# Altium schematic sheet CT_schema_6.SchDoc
size 274 x 160 mm
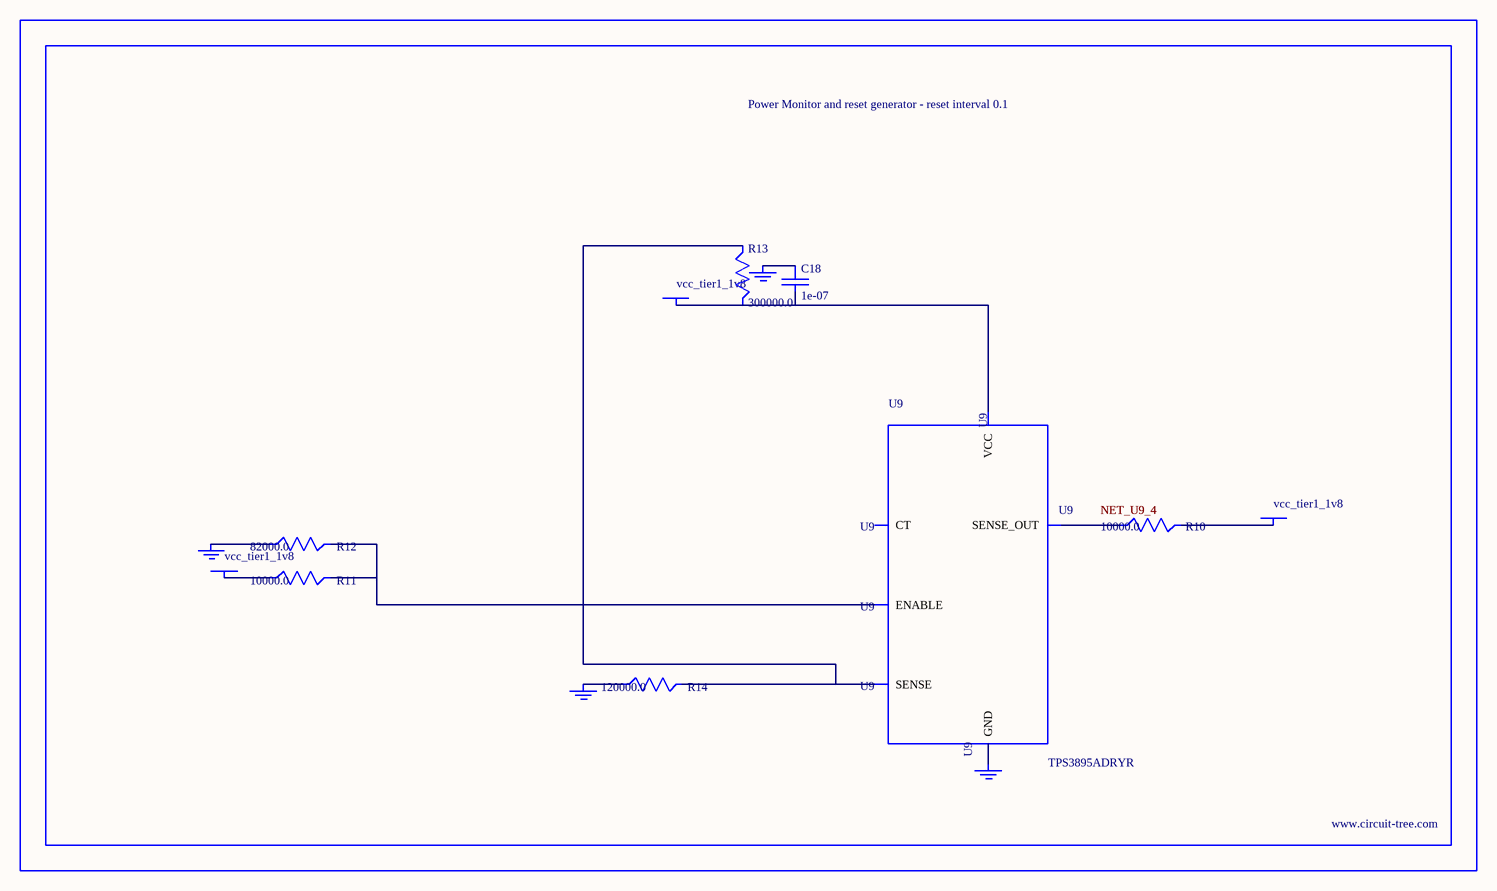
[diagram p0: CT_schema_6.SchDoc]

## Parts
BORDER5  (no value)
C18  1e-07  [C0402]
GND_INSTANCE_5_0  (no value)
GND_INSTANCE_5_1  (no value)
GND_INSTANCE_5_2  (no value)
GND_INSTANCE_5_3  (no value)
POWER_INSTANCE_5_0  vcc_tier1_1v8
POWER_INSTANCE_5_1  vcc_tier1_1v8
POWER_INSTANCE_5_2  vcc_tier1_1v8
R10  10000.0  [R0603]
R11  10000.0  [R0603]
R12  82000.0  [R0603]
R13  300000.0  [R0603]
R14  120000.0  [R0603]
U9  TPS3895ADRYR  [SON-6]

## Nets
NetC18_1: C18.1 GND_INSTANCE_5_2.0(GND)
NetC18_2: C18.2 POWER_INSTANCE_5_2.0(PWR) R13.2 U9.6(VCC)
NetGND_INSTANCE_5_0_0: GND_INSTANCE_5_0.0(GND) R12.1
NetGND_INSTANCE_5_1_0: GND_INSTANCE_5_1.0(GND) R14.1
NetGND_INSTANCE_5_3_0: GND_INSTANCE_5_3.0(GND) U9.2(GND)
NetPOWER_INSTANCE_5_0_0: POWER_INSTANCE_5_0.0(PWR) R11.1
NetPOWER_INSTANCE_5_1_0: POWER_INSTANCE_5_1.0(PWR) R10.2
NetR10_1: R10.1 U9.4(SENSE_OUT)
NetR11_2: R11.2 R12.2 U9.1(ENABLE)
NetR13_1: R13.1 R14.2 U9.3(SENSE)

Not connected (* = marked no-connect by the designer): U9 5(CT)

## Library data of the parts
BORDER5 = BORDER_PAGE5
C18 = C0402C104K3RACTU
GND_INSTANCE_5_0-GND_INSTANCE_5_3 = GND
POWER_INSTANCE_5_0-POWER_INSTANCE_5_2 = PWR
R10 R11 = RC0603JR-0710KL
R12 = RC0603JR-0782KL
R13 = RC0603JR-07300KL
R14 = RC0603JR-07120KL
